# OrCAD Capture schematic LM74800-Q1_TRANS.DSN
size C; title: TPS259827LNRGE: 2.7-24 V, 15A, 2.7mOhm Smart eFuse With; rev: 1.0; note: Datasheet: SNOSD95    EVM: PSIL106; note: LM74800-Q1- Ideal Diode Controller with Load Dump Protection; note: Transient Fault Management
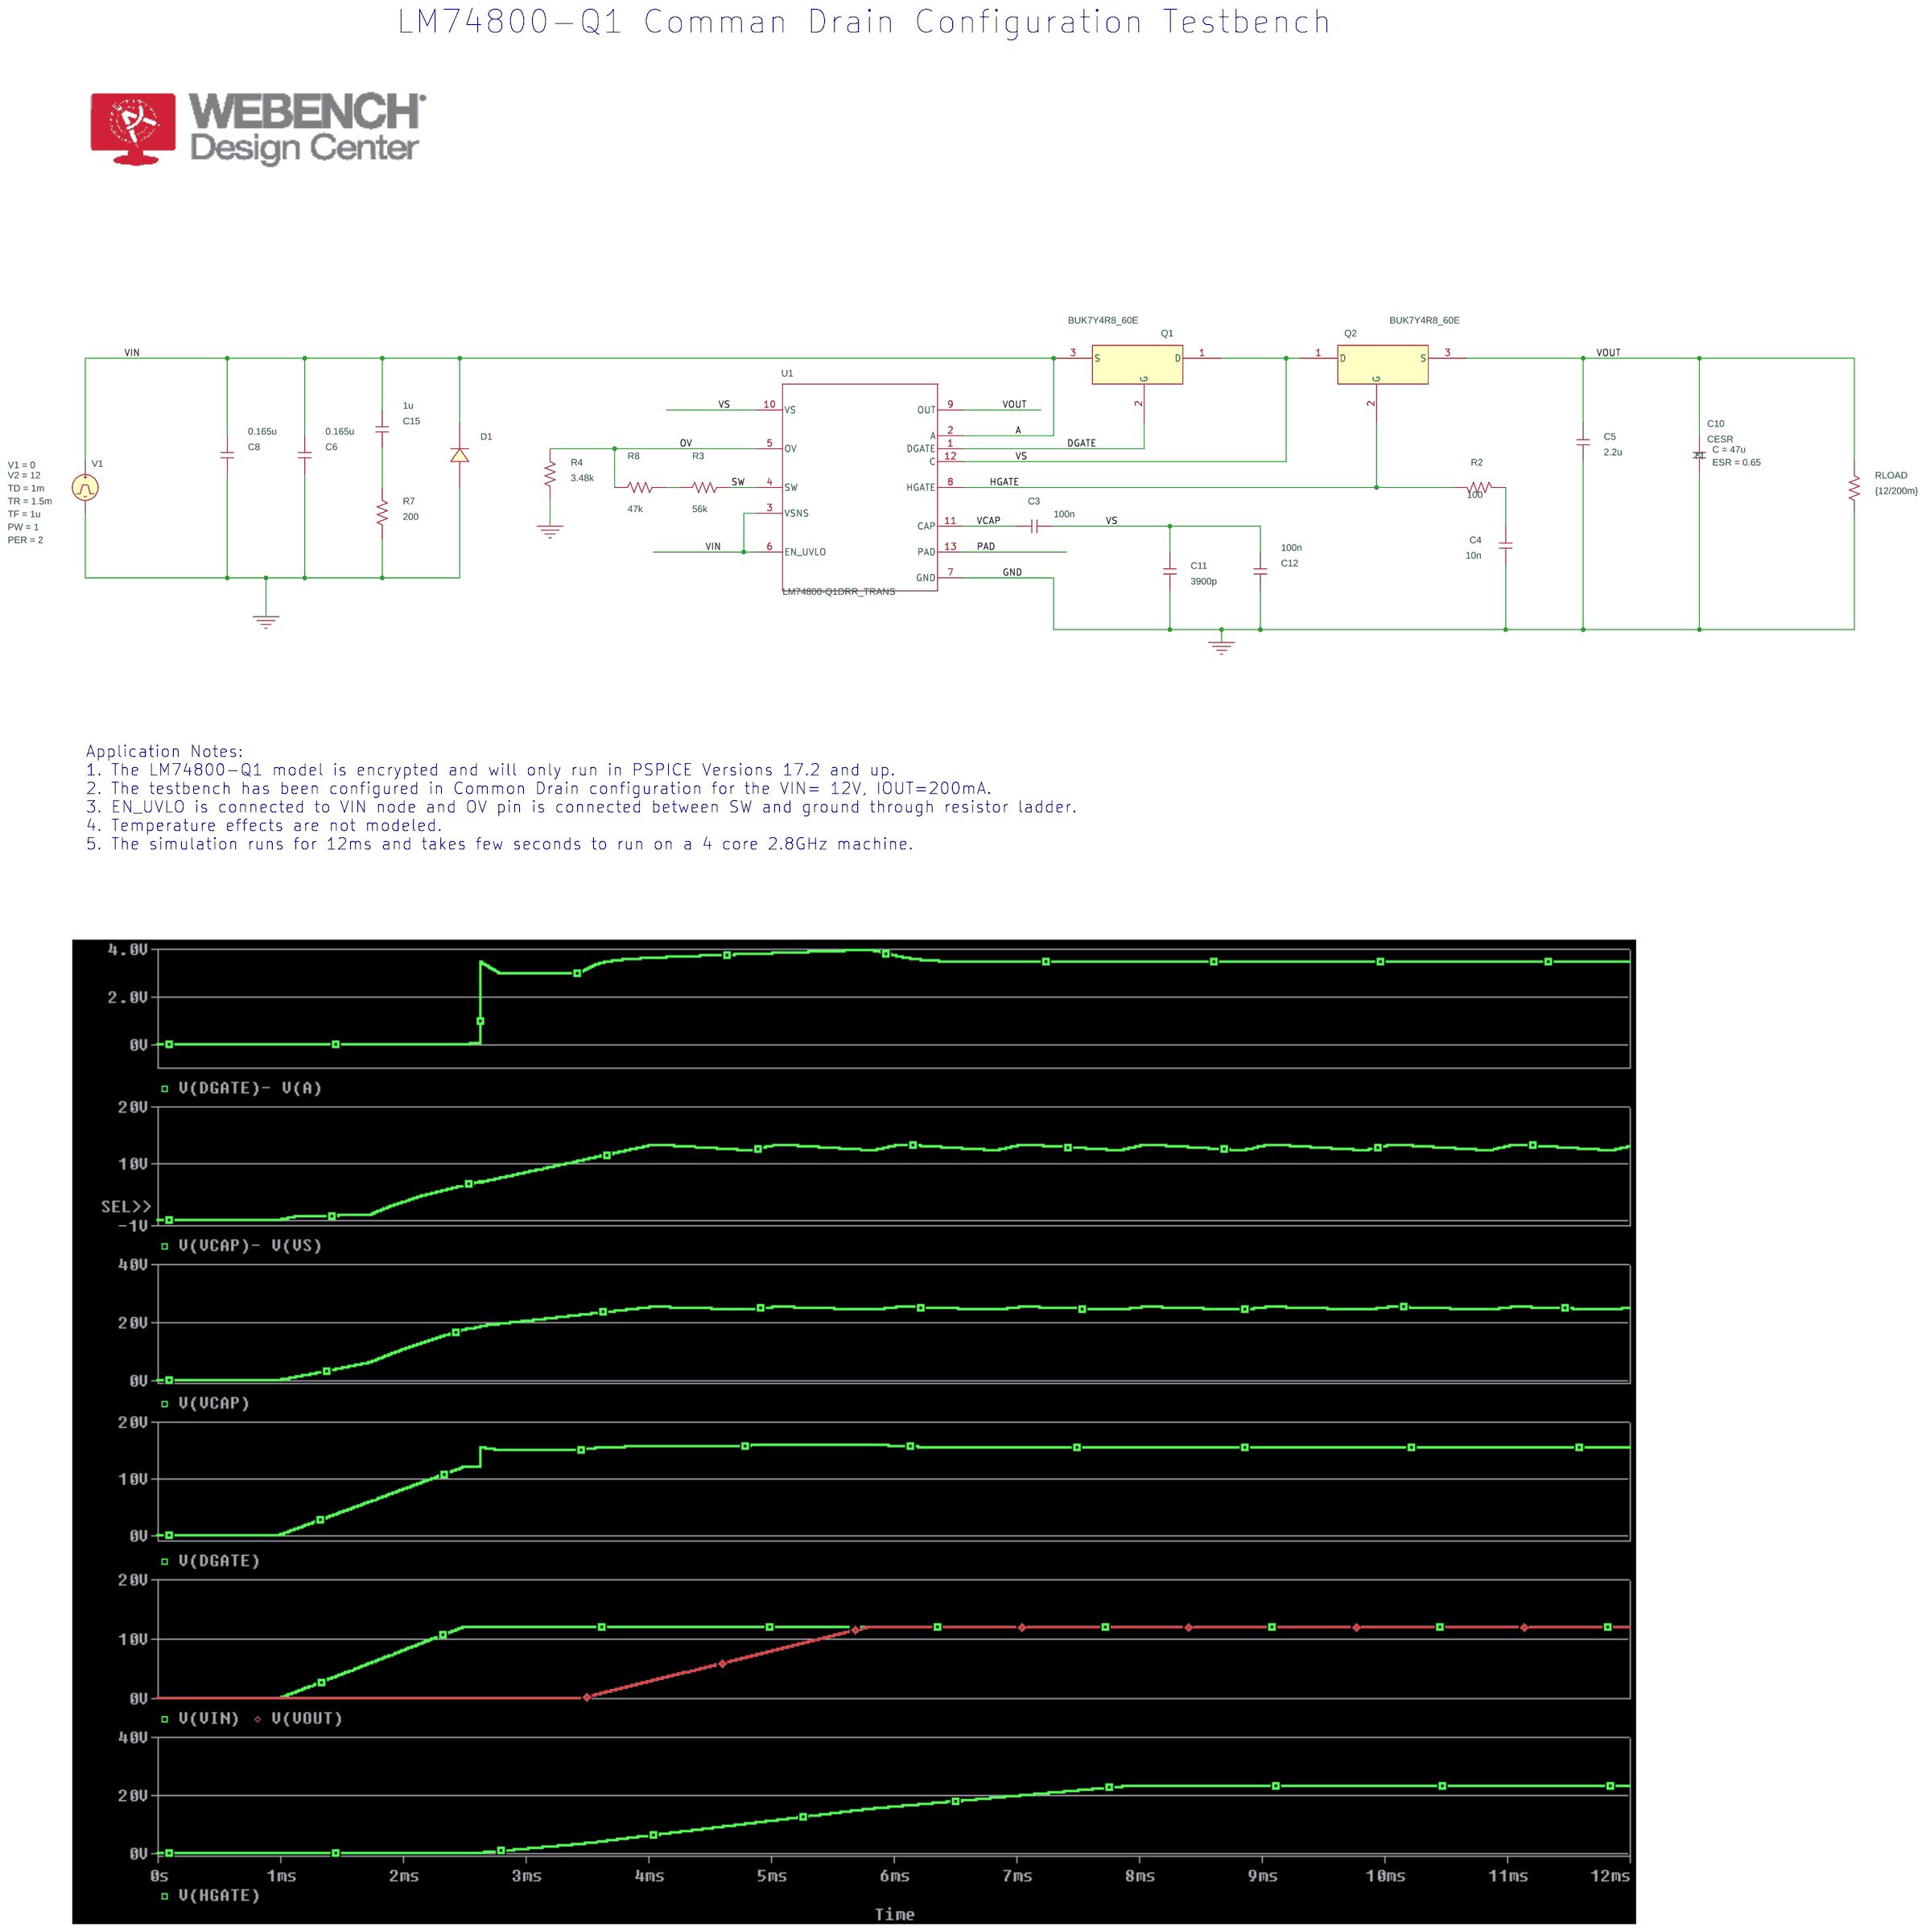
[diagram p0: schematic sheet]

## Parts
C3  100n  [RAD/CK05]
C4  10n  [RAD/CK05]
C5  2.2u  [RAD/CK05]
C6  0.165u  [RAD/CK05]
C8  0.165u  [RAD/CK05]
C10  CESR
C11  3900p  [RAD/CK05]
C12  100n  [RAD/CK05]
C15  1u  [RAD/CK05]
D1  SMBJ33A
Q1  BUK7Y4R8_60E
Q2  BUK7Y4R8_60E
R2  100  [AX/RC05]
R3  56k  [AX/RC05]
R4  3.48k  [AX/RC05]
R7  200  [AX/RC05]
R8  47k  [AX/RC05]
RLOAD  {12/200m}  [AX/RC05]
U1  LM74800-Q1DRR_TRANS  [DRR0012E]
V1  VPULSE

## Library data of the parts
C3-C6 C8 C11 C12 C15 = C
C10 = CESR: C: 47u; ESL: 0; ESR: 0.65; PSpiceTemplate: X^@REFDES %1 %2 @MODEL PARAMS: ?C|C=@C||C=10U| ?ESR|ESR=@ESR||ESR=2M| ?IC|IC=@IC||IC=0|
D1 = SMBJ33A
Q1 Q2 = BUK7Y4R8_60E
R2-R4 R7 R8 RLOAD = R
U1 = LM74800-Q1DRR_TRANS
V1 = VPULSE: PER: 2; PW: 1; TD: 1m; TF: 1u; TR: 1.5m; V1: 0; V2: 12

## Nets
0: C4.1 C5.1 C6.2 C8.2 C10.2 C11.1 C12.2 D1.2(A) R4.1 R7.1 RLOAD.2 U1.7(GND) V1.2(-)
A: C6.1 C8.1 C15.1 D1.1(C) Q1.3(S) U1.2(A) U1.3(VSNS) U1.6(EN_UVLO) V1.1(+)
DGATE: Q1.2(G) U1.1(DGATE)
HGATE: Q2.2(G) R2.2 U1.8(HGATE)
OV: R4.2 R8.2 U1.5(OV)
PAD: U1.13(PAD)
SW: R3.1 U1.4(SW)
VCAP: C3.1 U1.11(CAP)
VOUT: C5.2 C10.1 Q2.3(S) RLOAD.1 U1.9(OUT)
VS: C3.2 C11.2 C12.1 Q1.1(D) Q2.1(D) U1.10(VS) U1.12(C)
N16087175: C15.2 R7.2
N16553788: C4.2 R2.1
N16607349: R3.2 R8.1

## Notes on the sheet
- LM74800-Q1 Comman Drain Configuration Testbench
- Application Notes:
  1. The LM74800-Q1 model is encrypted and will only run in PSPICE Versions 17.2 and up.
  2. The testbench has been configured in Common Drain configuration for the VIN= 12V, IOUT=200mA.
  3. EN_UVLO is connected to VIN node and OV pin is connected between SW and ground through resistor ladder.
  4. Temperature effects are not modeled.
  5. The simulation runs for 12ms and takes few seconds to run on a 4 core 2.8GHz machine.
